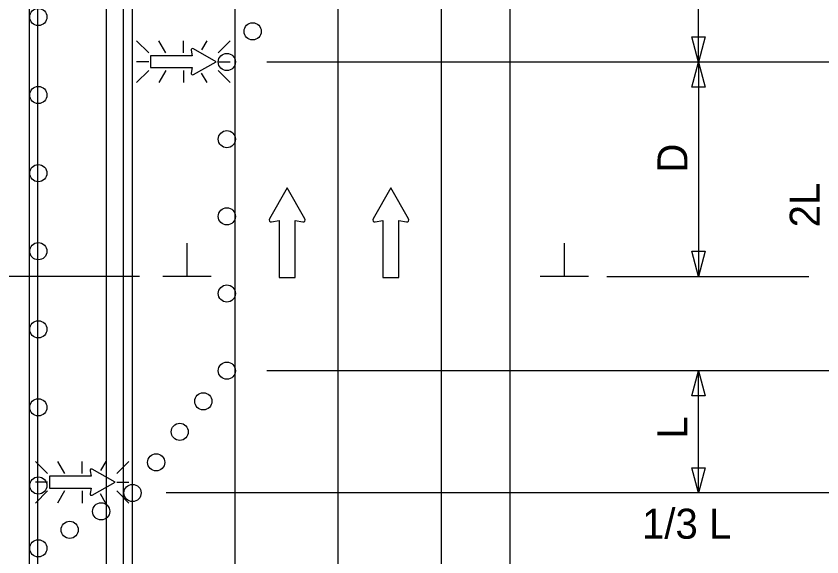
# Model space of a CAD drawing. Extents: x 16731 to 18475, y 7003 to 8262.
# Drawn here: x 17014.2 to 17202, y 7661 to 7787.1 of the extents above; entities that cross this region are included whole.
import ezdxf

# ---------------------------------------------------------------- set-up
doc = ezdxf.new("R2010")
doc.units = 0
for name, color, linetype in [('ALI_LEGAL_EX', 7, 'Continuous'), ('MT_SCRATCH_LEVEL_E', 7, 'Continuous'), ('PAVT_EDGE_EX', 7, 'Continuous'), ('TRAFFIC_SIGNS_PR', 7, 'Continuous'), ('TYPICAL_TEXT_DIMEN_PR', 7, 'Continuous')]:
    doc.layers.add(name, color=color, linetype=linetype)

msp = doc.modelspace()

# ---------------------------------------------------------------- linework, layer by layer
at = {"layer": 'ALI_LEGAL_EX'}
for p, q in [((17019.24, 7388.68), (17019.24, 8211.76)), ((17039.24, 7388.68), (17039.24, 8211.76)), ((17065.24, 7388.68), (17065.24, 8211.76)), ((17089.24, 7388.68), (17089.24, 8211.76))]:
    msp.add_line(p, q, dxfattribs=at)
for points in [[(17019.24, 7688.68), (17019.24, 7713.68)], [(17039.24, 7688.68), (17039.24, 7713.68)], [(17089.24, 7688.68), (17089.24, 7713.68)]]:
    msp.add_lwpolyline(points, dxfattribs=at)
at = {"layer": 'MT_SCRATCH_LEVEL_E'}
for p, q in [((17077.34, 7747.05), (17073.23, 7739.81)), ((17077.34, 7747.05), (17073.23, 7739.81)), ((17081.49, 7739.81), (17077.34, 7747.05)), ((17081.49, 7739.81), (17077.34, 7747.05)), ((17101.51, 7747.05), (17097.4, 7739.81)), ((17101.51, 7747.05), (17097.4, 7739.81)), ((17105.66, 7739.81), (17101.51, 7747.05)), ((17105.66, 7739.81), (17101.51, 7747.05)), ((17073.71, 7739.12), (17075.49, 7739.44)), ((17073.71, 7739.12), (17075.49, 7739.44)), ((17075.49, 7739.44), (17075.49, 7726.18)), ((17075.49, 7739.44), (17075.49, 7726.18)), ((17079.23, 7726.18), (17079.23, 7739.44)), ((17079.23, 7739.44), (17081.01, 7739.12)), ((17079.23, 7726.18), (17079.23, 7739.44)), ((17079.23, 7739.44), (17081.01, 7739.12)), ((17097.88, 7739.12), (17099.66, 7739.44)), ((17097.88, 7739.12), (17099.66, 7739.44)), ((17099.66, 7739.44), (17099.66, 7726.18)), ((17099.66, 7739.44), (17099.66, 7726.18)), ((17103.4, 7726.18), (17103.4, 7739.44)), ((17103.4, 7739.44), (17105.18, 7739.12)), ((17103.4, 7726.18), (17103.4, 7739.44)), ((17103.4, 7739.44), (17105.18, 7739.12)), ((17075.49, 7726.18), (17079.23, 7726.18)), ((17075.49, 7726.18), (17079.23, 7726.18)), ((17099.66, 7726.18), (17103.4, 7726.18)), ((17099.66, 7726.18), (17103.4, 7726.18))]:
    msp.add_line(p, q, dxfattribs=at)
for centre, start, end in [((17073.64, 7739.58), 150.4248, 279.9638), ((17073.64, 7739.58), 150.4248, 279.9638), ((17081.08, 7739.58), 260.0362, 29.7731), ((17081.08, 7739.58), 260.0362, 29.7731), ((17097.81, 7739.58), 150.4248, 279.9638), ((17097.81, 7739.58), 150.4248, 279.9638), ((17105.25, 7739.58), 260.0362, 29.7731), ((17105.25, 7739.58), 260.0362, 29.7731)]:
    msp.add_arc(centre, 0.463, start, end, dxfattribs=at)
at = {"layer": 'PAVT_EDGE_EX'}
for p, q in [((17035.15, 8262.34), (17035.15, 7433.15)), ((17017.24, 8211.76), (17017.24, 7353.85)), ((17041.24, 8211.76), (17041.24, 7353.85)), ((17113.24, 8211.76), (17113.24, 7353.85)), ((17129.24, 8211.76), (17129.24, 7353.85))]:
    msp.add_line(p, q, dxfattribs=at)
at = {"layer": 'TRAFFIC_SIGNS_PR'}
for p, q in [((17045.09, 7778.51), (17042.27, 7781.33)), ((17047.38, 7781.33), (17049.01, 7778.51)), ((17053.17, 7778.51), (17053.17, 7781.33)), ((17058.64, 7781.33), (17057.43, 7779.24)), ((17064.08, 7781.33), (17061.26, 7778.51)), ((17045.09, 7776.48), (17042.27, 7776.48)), ((17061.26, 7776.48), (17064.08, 7776.48)), ((17045.09, 7774.44), (17042.27, 7771.62)), ((17049.04, 7774.44), (17047.41, 7771.62)), ((17053.17, 7774.44), (17053.17, 7771.62)), ((17057.35, 7773.81), (17058.62, 7771.62)), ((17064.08, 7771.63), (17061.26, 7774.44)), ((17021.51, 7680.42), (17018.69, 7683.24)), ((17023.8, 7683.24), (17025.43, 7680.42)), ((17029.59, 7680.42), (17029.59, 7683.24)), ((17035.06, 7683.24), (17033.85, 7681.15)), ((17040.49, 7683.24), (17037.68, 7680.42)), ((17021.51, 7678.39), (17018.69, 7678.39)), ((17037.68, 7678.39), (17040.49, 7678.39)), ((17021.51, 7676.36), (17018.69, 7673.54)), ((17025.46, 7676.36), (17023.83, 7673.54)), ((17029.59, 7676.36), (17029.59, 7673.54)), ((17033.77, 7675.73), (17035.03, 7673.54)), ((17040.49, 7673.54), (17037.68, 7676.36))]:
    msp.add_line(p, q, dxfattribs=at)
for points in [[(17055, 7779.16), (17055.23, 7777.86), (17045.51, 7777.86), (17045.51, 7775.12), (17055.23, 7775.12), (17055, 7773.82)], [(17055.5, 7773.46), (17060.81, 7776.48), (17055.5, 7779.52)], [(17031.92, 7675.38), (17037.23, 7678.39), (17031.92, 7681.43)], [(17031.42, 7681.07), (17031.65, 7679.78), (17021.92, 7679.78), (17021.92, 7677.03), (17031.65, 7677.03), (17031.42, 7675.73)]]:
    msp.add_lwpolyline(points, dxfattribs=at)
for centre in [(17019.34, 7786.92), (17069.31, 7783.55), (17063.31, 7776.41), (17019.34, 7768.7), (17063.31, 7758.4), (17019.34, 7750.49), (17063.31, 7740.4), (17019.34, 7732.27), (17063.31, 7722.4), (17019.34, 7714.06), (17063.31, 7704.4), (17057.81, 7697.27), (17019.34, 7695.85), (17052.32, 7690.15), (17046.82, 7683.02), (17019.34, 7677.63), (17041.32, 7675.89), (17033.99, 7671.59), (17026.67, 7667.28), (17019.34, 7662.97)]:
    msp.add_circle(centre, 2, dxfattribs=at)
for centre, start, end in [((17055.33, 7779.22), 61.4833, 189.9593), ((17055.33, 7773.76), 170.7308, 298.8916), ((17031.75, 7681.13), 61.4833, 189.9593), ((17031.75, 7675.68), 170.7308, 298.8916)]:
    msp.add_arc(centre, 0.341, start, end, dxfattribs=at)
at = {"layer": 'TYPICAL_TEXT_DIMEN_PR'}
for p, q in [((17173.24, 7776.39), (17173.24, 7806.97)), ((17173.24, 7776.39), (17171.67, 7782.26)), ((17171.67, 7782.26), (17173.24, 7782.26)), ((17173.24, 7782.26), (17174.81, 7782.26)), ((17174.81, 7782.26), (17173.24, 7776.39)), ((17208.6, 7776.39), (17072.6, 7776.39)), ((17171.67, 7770.53), (17173.24, 7776.39)), ((17173.24, 7776.39), (17173.24, 7726.39)), ((17173.24, 7776.39), (17174.81, 7770.53)), ((17173.24, 7770.53), (17171.67, 7770.53)), ((17174.81, 7770.53), (17173.24, 7770.53)), ((17054.03, 7726.39), (17054.03, 7734.18)), ((17142, 7726.39), (17142, 7734.18)), ((17173.24, 7726.39), (17171.67, 7732.26)), ((17171.67, 7732.26), (17173.24, 7732.26)), ((17173.24, 7732.26), (17174.81, 7732.26)), ((17174.81, 7732.26), (17173.24, 7726.39)), ((17042.95, 7726.39), (16867.24, 7726.39)), ((17059.66, 7726.39), (17048.41, 7726.39)), ((17147.62, 7726.39), (17136.37, 7726.39)), ((17151.87, 7726.39), (17199.01, 7726.39)), ((17208.6, 7704.4), (17072.6, 7704.4)), ((17171.67, 7698.54), (17173.24, 7704.4)), ((17173.24, 7675.89), (17173.24, 7704.4)), ((17173.24, 7704.4), (17174.81, 7698.54)), ((17173.24, 7698.54), (17171.67, 7698.54)), ((17174.81, 7698.54), (17173.24, 7698.54)), ((17173.24, 7675.89), (17171.67, 7681.76)), ((17171.67, 7681.76), (17173.24, 7681.76)), ((17173.24, 7681.76), (17174.81, 7681.76)), ((17174.81, 7681.76), (17173.24, 7675.89)), ((17208.6, 7675.89), (17049.19, 7675.89))]:
    msp.add_line(p, q, dxfattribs=at)

# ---------------------------------------------------------------- texts
for s, p in [('D', (17170.68, 7750.61)), ('2L', (17201.53, 7737.84)), ('L', (17170.68, 7688.54))]:
    msp.add_text(s, height=7, rotation=90, dxfattribs=at).set_placement(p)
msp.add_text('1/3 L', height=7, dxfattribs=at).set_placement((17160.08, 7665.21))

doc.saveas('drawing.dxf')
